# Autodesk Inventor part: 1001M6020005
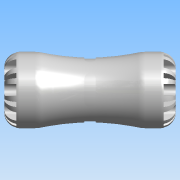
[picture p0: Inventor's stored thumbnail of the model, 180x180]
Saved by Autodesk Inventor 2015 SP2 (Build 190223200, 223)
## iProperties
Created: 2016-12
Part Number: 1001M6020005
Material: PVC-Piping
Description: PLASSON COUPLER METRIC TO IMPERIAL 20X1/2" SERIES 1
Document SubType Name: Modeling
Designer: KIM
Mass: 95.2094 g
Surface Area: 200.83 cm^2
Volume: 68.0067 cm^3
Density: 1.4 g/cm^3
Appearance: Smooth - White
ILogicFactory: False
Author: KIM
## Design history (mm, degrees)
derived "1001M.ipt"
feature "Solid1::1001M.ipt"
tag "TaggingFeature1"
body "Solid1"
other parameters: "d2" = 45, "d11" = 6.4, "d13" = 6.4, "d14" = 0, "d16" = 360 deg, "d18" = 8 deg, "d19" = 0.4, "d20" = 8 deg, "d21" = 0.4, "d23" = 0, "d25" = 360 deg, "d27" = 16.4, "d28" = 6, "d29" = 6, "d30" = 12.544, "d31" = 0, "d33" = 0, "d37" = 18.4, "d38" = 0.41, "d45" = 18.4, "d46" = 34.85, "d47" = 41, "d50" = 360 deg, "d54" = 0.513, "d61" = 25, "d64" = 92, "d66" = 1.05833, "d67" = 46, "d70" = 6.4, "d72" = 6.4, "d73" = 0, "d75" = 360 deg, "d77" = 8 deg, "d78" = 8 deg, "d79" = 0.4, "d80" = 0.4, "d82" = 0, "d84" = 360 deg, "d87" = 25, "d93" = 12.7, "E_" = 41, "H_" = 92, "l_" = 45, "d_1" = 12.7, "d12" = 25, "d42" = 41, "d52" = 8, "d68" = 41, "d69" = 25, "d71" = 8
